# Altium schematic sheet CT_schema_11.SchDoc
size 741 x 377 mm
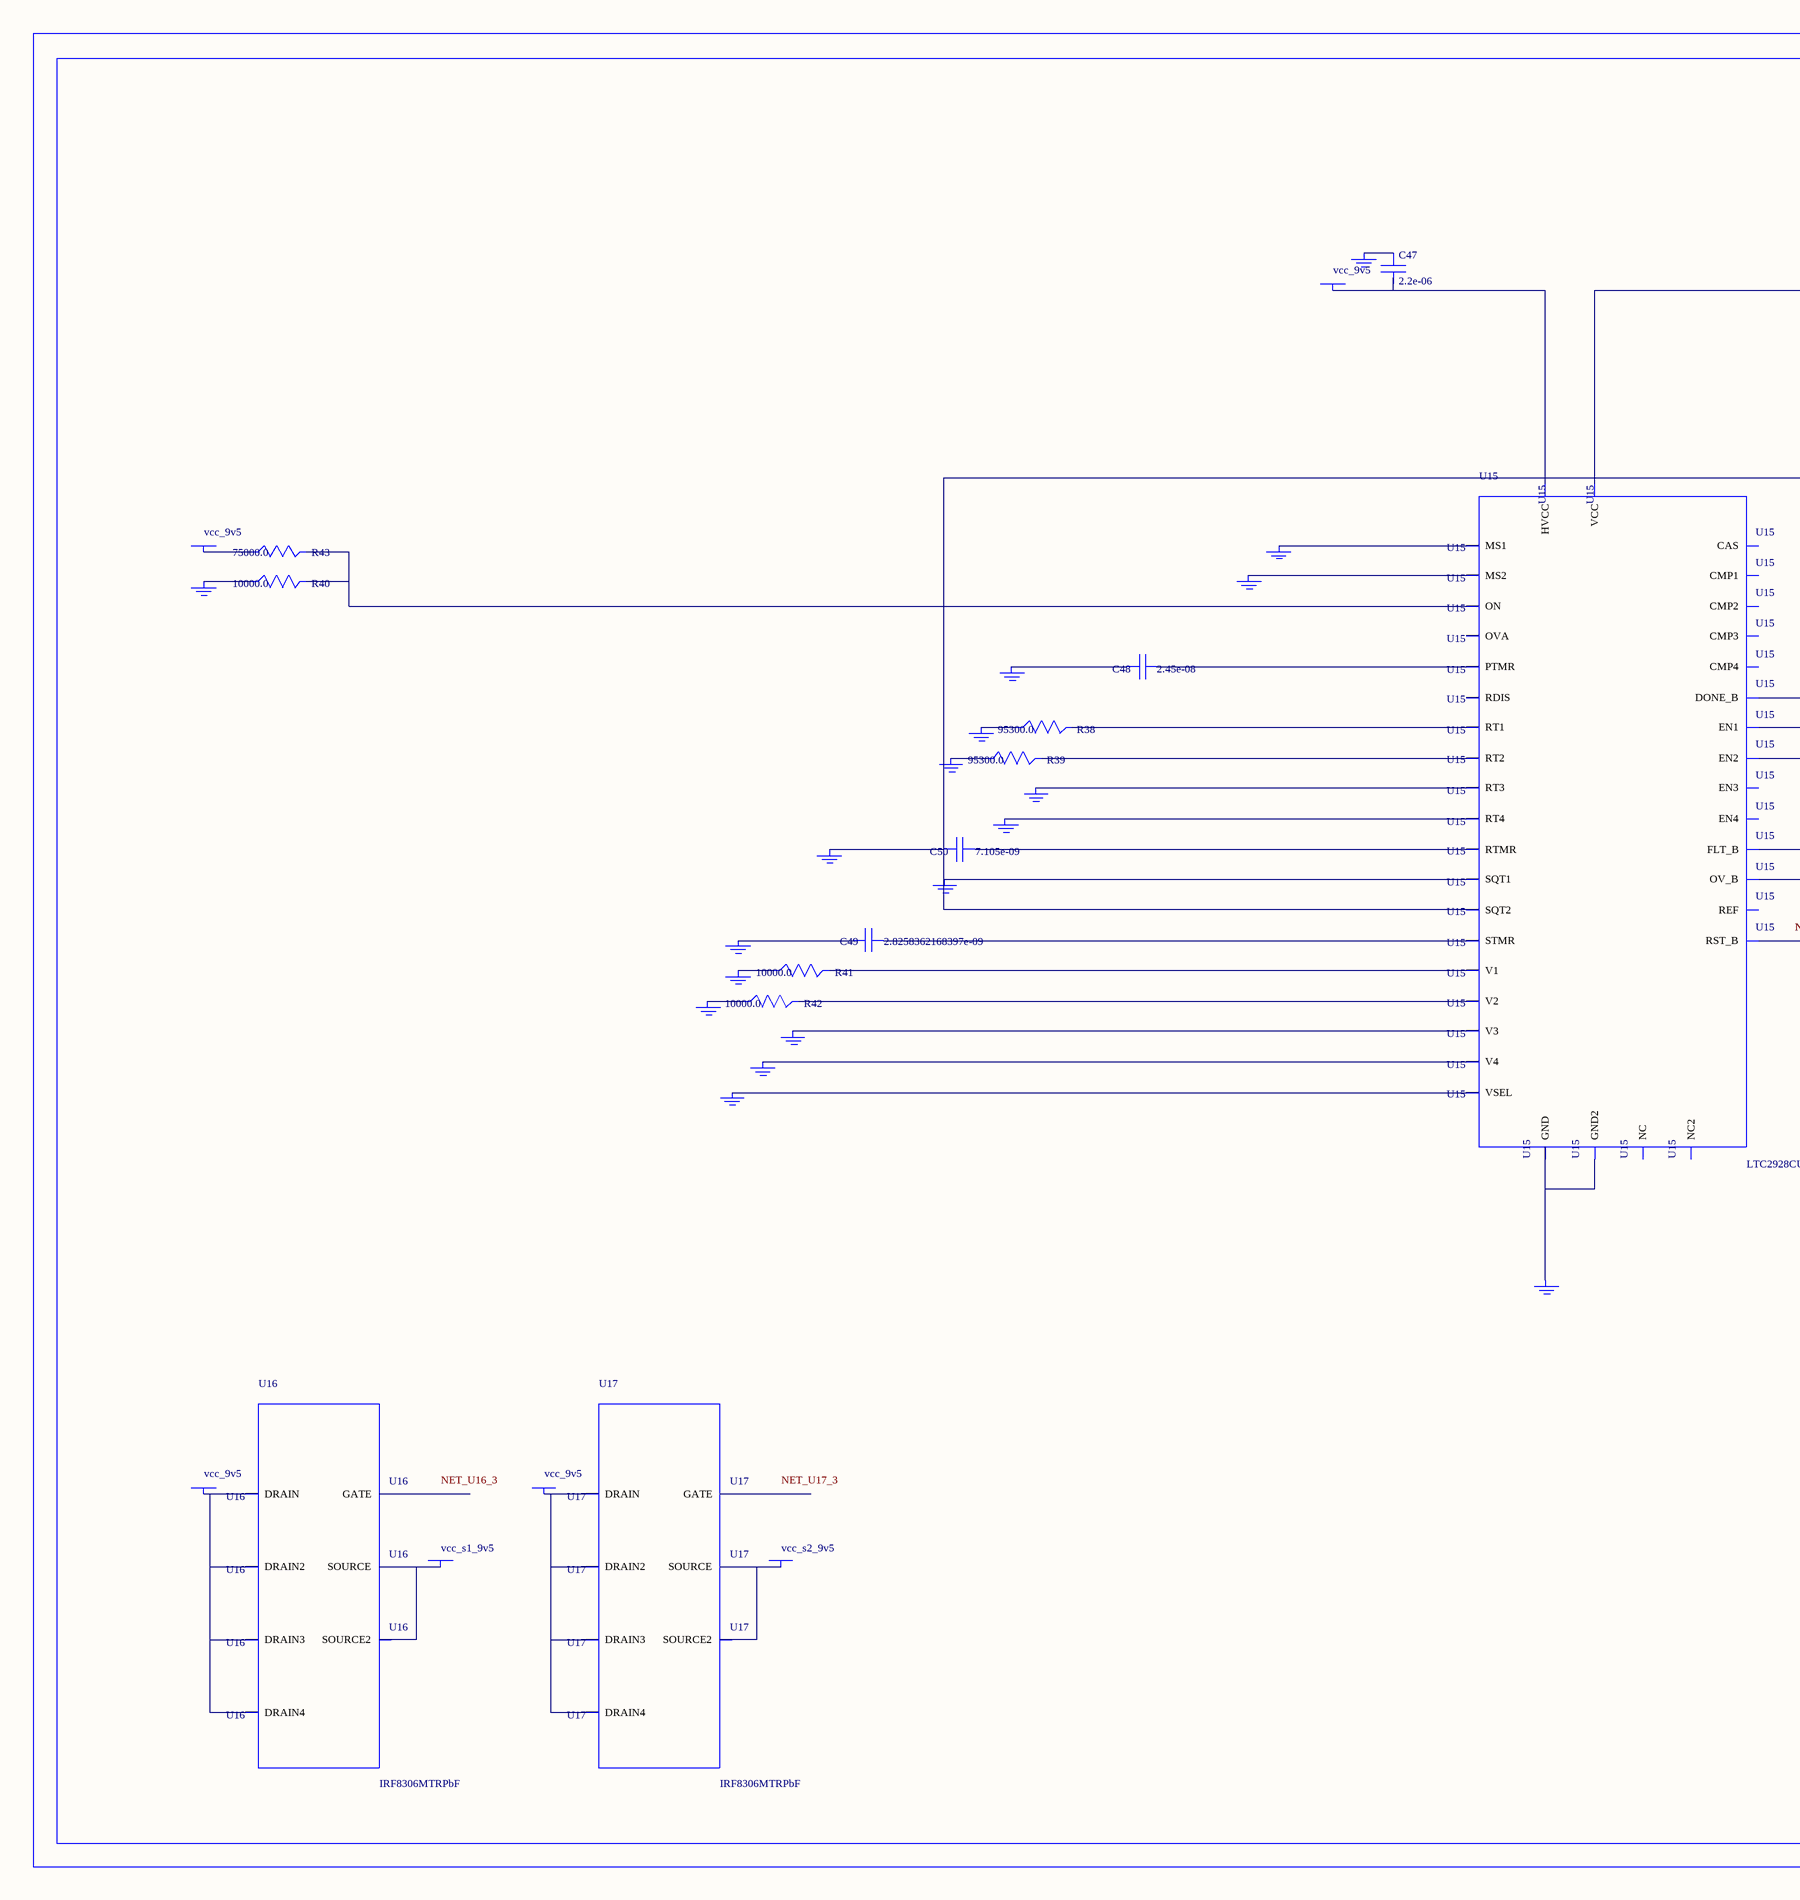
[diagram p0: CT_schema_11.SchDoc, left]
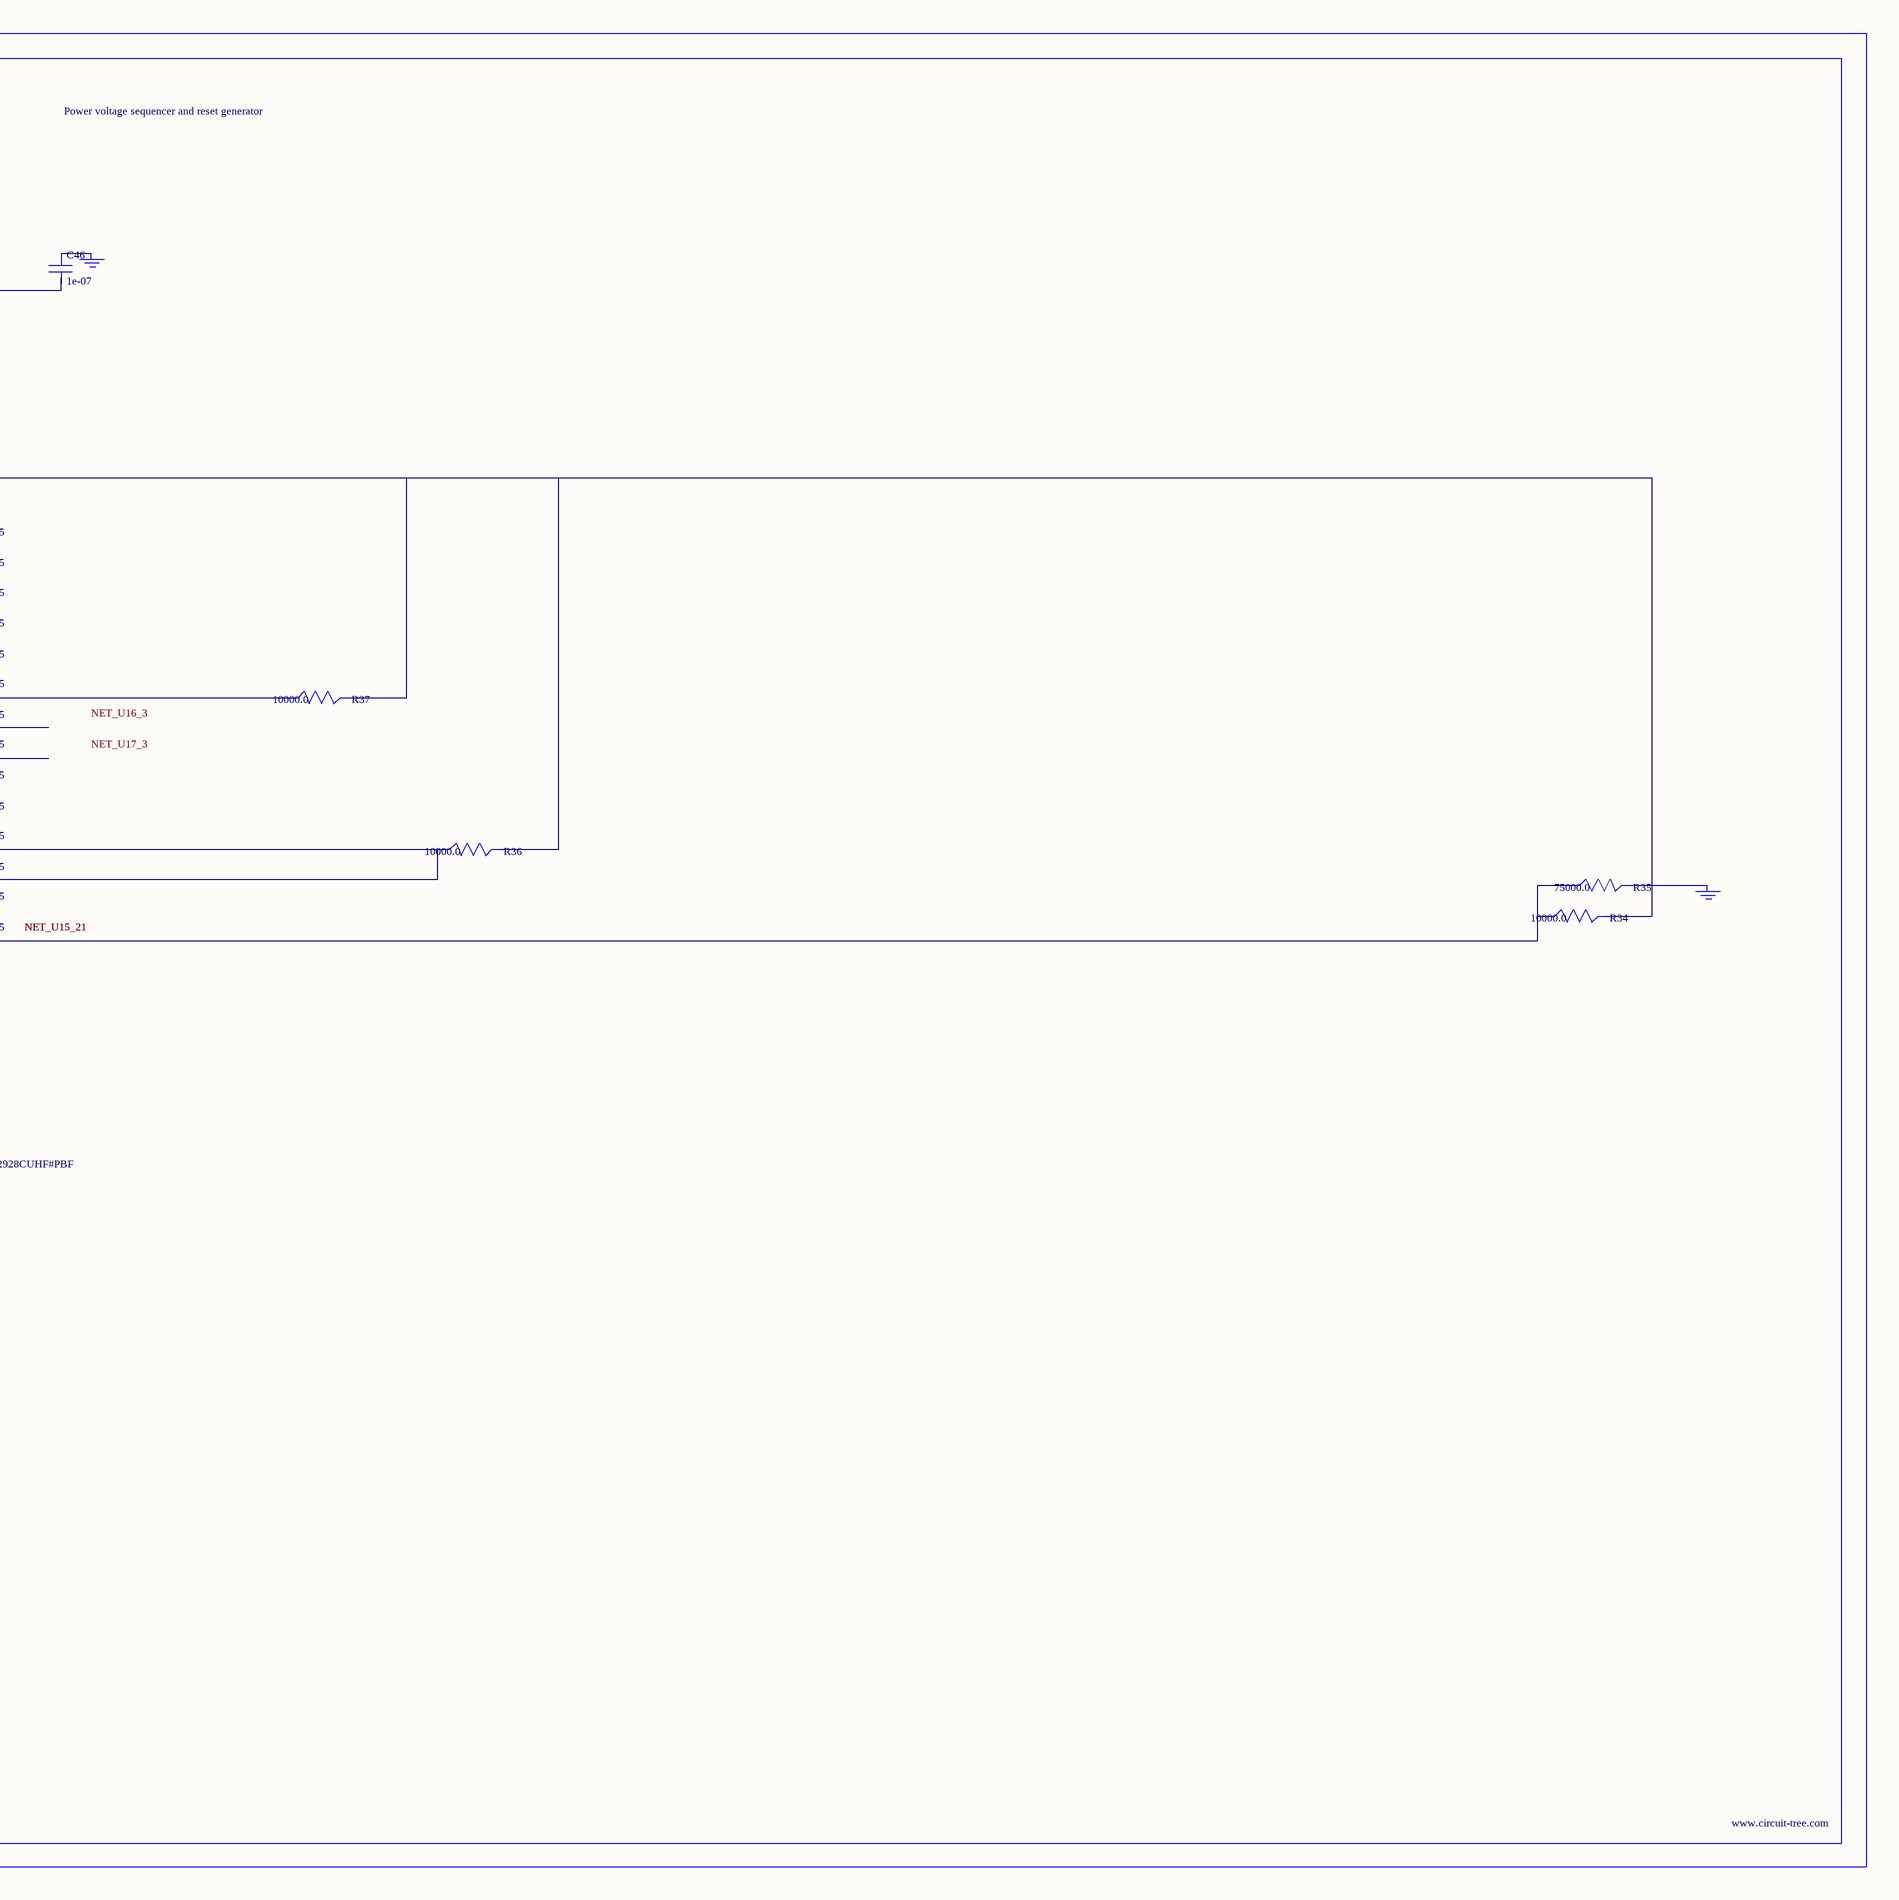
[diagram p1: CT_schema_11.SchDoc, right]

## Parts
BORDER10  (no value)
C46  1e-07  [C0402]
C47  2.2e-06  [C0603]
C48  2.45e-08  [R0603]
C49  2.8258362168397e-09  [R0603]
C50  7.105e-09  [R0603]
GND_INSTANCE_10_0  (no value)
GND_INSTANCE_10_1  (no value)
GND_INSTANCE_10_2  (no value)
GND_INSTANCE_10_3  (no value)
GND_INSTANCE_10_4  (no value)
GND_INSTANCE_10_5  (no value)
GND_INSTANCE_10_6  (no value)
GND_INSTANCE_10_7  (no value)
GND_INSTANCE_10_8  (no value)
GND_INSTANCE_10_9  (no value)
GND_INSTANCE_10_10  (no value)
GND_INSTANCE_10_11  (no value)
GND_INSTANCE_10_12  (no value)
GND_INSTANCE_10_13  (no value)
GND_INSTANCE_10_14  (no value)
GND_INSTANCE_10_15  (no value)
GND_INSTANCE_10_16  (no value)
GND_INSTANCE_10_17  (no value)
GND_INSTANCE_10_18  (no value)
GND_INSTANCE_10_19  (no value)
POWER_INSTANCE_10_0  vcc_9v5
POWER_INSTANCE_10_1  vcc_9v5
POWER_INSTANCE_10_2  vcc_9v5
POWER_INSTANCE_10_3  vcc_s1_9v5
POWER_INSTANCE_10_4  vcc_9v5
POWER_INSTANCE_10_5  vcc_s2_9v5
R34  10000.0  [R0603]
R35  75000.0  [R0603]
R36  10000.0  [R0603]
R37  10000.0  [R0603]
R38  95300.0  [R0603]
R39  95300.0  [R0603]
R40  10000.0  [R0603]
R41  10000.0  [R0603]
R42  10000.0  [R0603]
R43  75000.0  [R0603]
U15  LTC2928CUHF#PBF  [QFN-38_UHF]
U16  IRF8306MTRPbF  [IRF8306MTRPBF]
U17  IRF8306MTRPbF  [IRF8306MTRPBF]

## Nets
NetC46_1: C46.1 GND_INSTANCE_10_10.0(GND)
NetC46_2: C46.2 C50.2 GND_INSTANCE_10_5.0(GND) GND_INSTANCE_10_15.0(GND) R34.2 R36.2 R37.2 U15.10(SQT1) U15.11(SQT2) U15.22(VCC)
NetC47_1: C47.1 GND_INSTANCE_10_11.0(GND)
NetC47_2: C47.2 POWER_INSTANCE_10_1.0(PWR) U15.23(HVCC)
NetC48_1: C48.1 U15.27(PTMR)
NetC48_2: C48.2 GND_INSTANCE_10_14.0(GND)
NetC49_1: C49.1 U15.26(STMR)
NetC49_2: C49.2 GND_INSTANCE_10_13.0(GND)
NetC50_1: C50.1 U15.28(RTMR)
NetGND_INSTANCE_10_0_0: GND_INSTANCE_10_0.0(GND) R41.1
NetGND_INSTANCE_10_1_0: GND_INSTANCE_10_1.0(GND) R38.1
NetGND_INSTANCE_10_2_0: GND_INSTANCE_10_2.0(GND) R39.1
NetGND_INSTANCE_10_3_0: GND_INSTANCE_10_3.0(GND) U15.8(RT3)
NetGND_INSTANCE_10_4_0: GND_INSTANCE_10_4.0(GND) U15.9(RT4)
NetGND_INSTANCE_10_6_0: GND_INSTANCE_10_6.0(GND) U15.12(MS1)
NetGND_INSTANCE_10_7_0: GND_INSTANCE_10_7.0(GND) U15.13(MS2)
NetGND_INSTANCE_10_8_0: GND_INSTANCE_10_8.0(GND) R40.1
NetGND_INSTANCE_10_9_0: GND_INSTANCE_10_9.0(GND) R35.2
NetGND_INSTANCE_10_12_0: GND_INSTANCE_10_12.0(GND) U15.25(VSEL)
NetGND_INSTANCE_10_16_0: GND_INSTANCE_10_16.0(GND) U15.30(V4)
NetGND_INSTANCE_10_17_0: GND_INSTANCE_10_17.0(GND) U15.32(V3)
NetGND_INSTANCE_10_18_0: GND_INSTANCE_10_18.0(GND) R42.1
NetGND_INSTANCE_10_19_0: GND_INSTANCE_10_19.0(GND) U15.24(GND) U15.39(GND2)
NetPOWER_INSTANCE_10_0_0: POWER_INSTANCE_10_0.0(PWR) R43.1
NetPOWER_INSTANCE_10_2_0: POWER_INSTANCE_10_2.0(PWR) U16.1(DRAIN) U16.2(DRAIN2) U16.6(DRAIN3) U16.7(DRAIN4)
NetPOWER_INSTANCE_10_3_0: POWER_INSTANCE_10_3.0(PWR) U16.4(SOURCE) U16.5(SOURCE2)
NetPOWER_INSTANCE_10_4_0: POWER_INSTANCE_10_4.0(PWR) U17.1(DRAIN) U17.2(DRAIN2) U17.6(DRAIN3) U17.7(DRAIN4)
NetPOWER_INSTANCE_10_5_0: POWER_INSTANCE_10_5.0(PWR) U17.4(SOURCE) U17.5(SOURCE2)
NetR34_1: R34.1 R35.1 U15.21(RST_B)
NetR36_1: R36.1 U15.19(FLT_B) U15.20(OV_B)
NetR37_1: R37.1 U15.18(DONE_B)
NetR38_2: R38.2 U15.6(RT1)
NetR39_2: R39.2 U15.7(RT2)
NetR40_2: R40.2 R43.2 U15.16(ON)
NetR41_2: R41.2 U15.3(V1)
NetR42_2: R42.2 U15.38(V2)

Not connected (* = marked no-connect by the designer): U15 1(OVA) 2(EN1) 4(NC) 5(REF) 14(RDIS) 15(CAS) 17(NC2) 29(EN4) 31(EN3) 33(CMP3) 34(CMP4) 35(CMP1) 36(CMP2) 37(EN2); U16 3(GATE); U17 3(GATE)

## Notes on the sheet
- Labels drawn without touching a wire or pin: NET_U16_3, NET_U17_3

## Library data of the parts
BORDER10 = BORDER_PAGE10
C46 = C0402C104K3RACTU
C47 = GRM188R61H225KE1115D
C48 = C48
C49 = C49
C50 = C50
GND_INSTANCE_10_0-GND_INSTANCE_10_19 = GND
POWER_INSTANCE_10_0-POWER_INSTANCE_10_5 = PWR
R34 R36 R37 R40-R42 = RC0603JR-0710KL
R35 R43 = RC0603JR-0775KL
R38 R39 = RC0603FR-0795K3L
